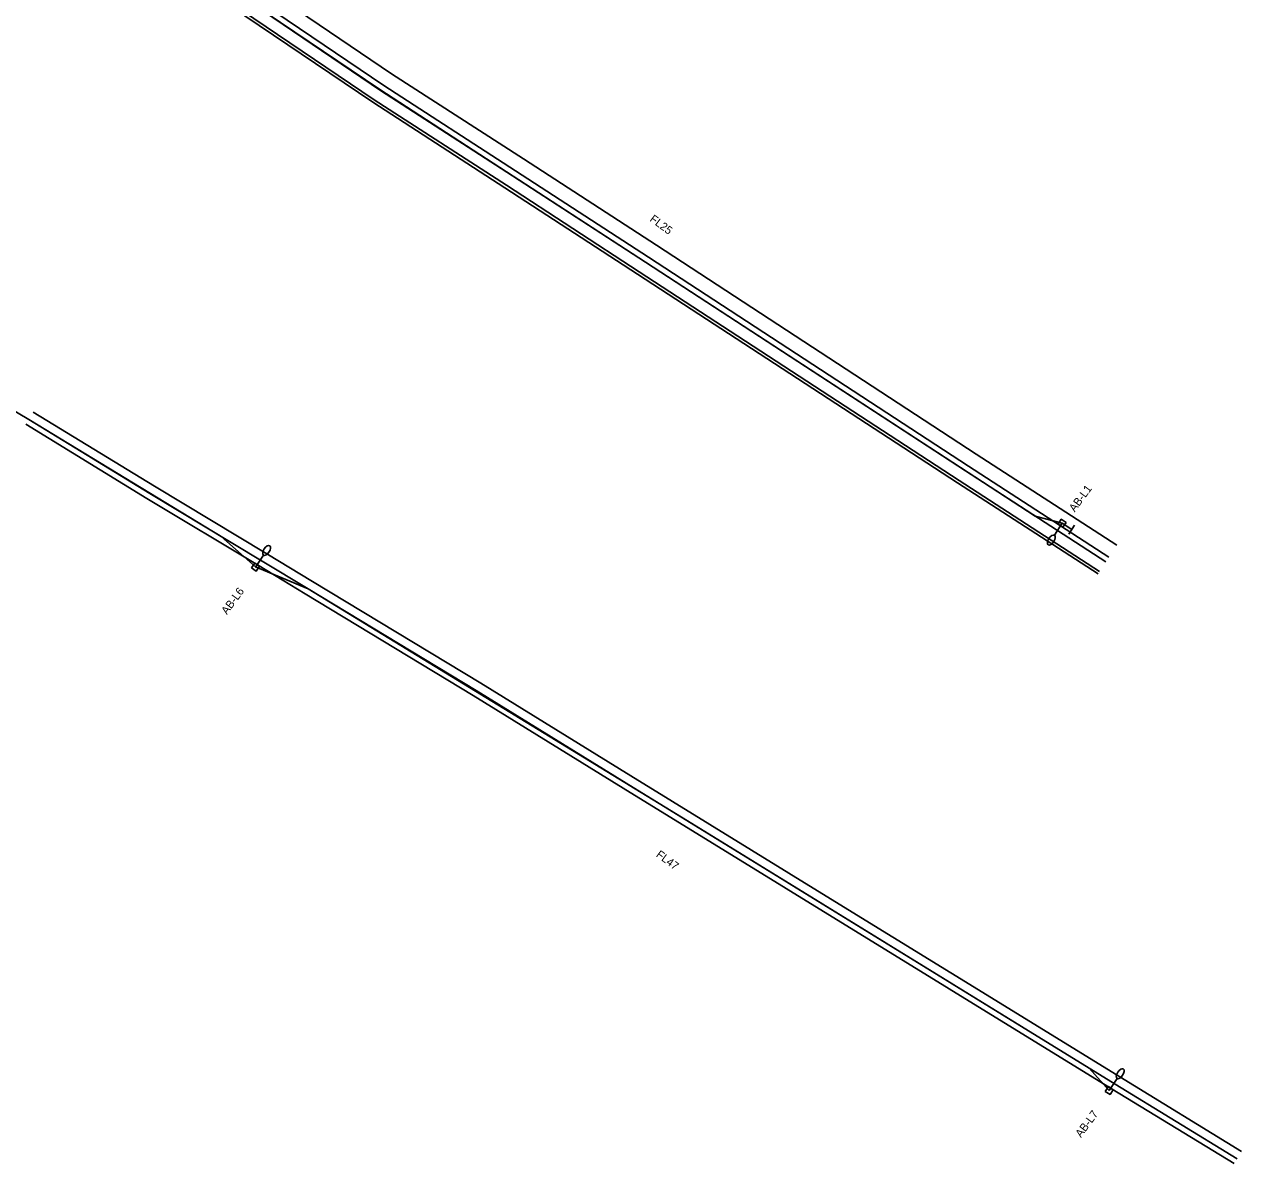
# Model space of a CAD drawing. Extents: x 1322666 to 1327584, y 458075 to 462260.
# Drawn here: x 1326186.9 to 1326612.7, y 458980.2 to 459378.6 of the extents above; entities that cross this region are included whole.
import ezdxf

# ---------------------------------------------------------------- set-up
doc = ezdxf.new("R2010")
doc.units = 0
for name, color, linetype in [('_CIVIL_CONSTRUCTION', 7, 'Continuous'), ('DR_P_Culvert3D', 7, 'Continuous'), ('PF_X_Ground_Line', 7, 'Continuous'), ('UT_X_Misc_Cells', 7, 'Continuous'), ('UT_X_Oil', 7, 'Continuous')]:
    doc.layers.add(name, color=color, linetype=linetype)

msp = doc.modelspace()

# ---------------------------------------------------------------- linework, layer by layer
at = {"layer": '_CIVIL_CONSTRUCTION'}
for p, q in [((1326549.86, 459204.14), (1326547.15, 459199.93)), ((1326267.75, 459188.82), (1326270.52, 459192.98)), ((1326566.35, 459005.74), (1326569.08, 459009.93))]:
    msp.add_line(p, q, dxfattribs=at)
for points in [[(1326551.24, 459204.44), (1326550.16, 459202.76), (1326548.48, 459203.84), (1326549.56, 459205.52)], [(1326266.36, 459188.54), (1326267.47, 459190.2), (1326269.14, 459189.1), (1326268.03, 459187.43)], [(1326564.97, 459005.45), (1326566.06, 459007.13), (1326567.73, 459006.03), (1326566.64, 459004.36)]]:
    msp.add_lwpolyline(points, close=True, dxfattribs=at)
for centre, major_axis in [((1326271.63, 459194.64), (1.11, 1.66)), ((1326546.07, 459198.25), (-1.08, -1.68)), ((1326570.18, 459011.61), (1.09, 1.67))]:
    msp.add_ellipse(centre, major_axis=major_axis, ratio=0.5, dxfattribs=at)
at = {"layer": 'DR_P_Culvert3D'}
for points in [[(1326568.96, 459196.54), (1326519.83, 459228.31), (1326407.95, 459301.35), (1326361.46, 459331.57), (1326315.37, 459361.38), (1326260.78, 459398.43), (1326183.72, 459451.96), (1326109.27, 459505.99), (1326047.67, 459552.79), (1325951.93, 459633.41), (1325920.86, 459660.88), (1325891.74, 459687.77), (1325870.28, 459708.32), (1325856.15, 459722.21), (1325848.08, 459730.28), (1325821.4, 459757.65)], [(1326562.99, 459187.31), (1326513.84, 459219.08), (1326401.95, 459292.13), (1326355.48, 459322.34), (1326309.3, 459352.21), (1326254.55, 459389.36), (1326177.35, 459442.99), (1326102.72, 459497.16), (1326040.79, 459544.19), (1325944.75, 459625.08), (1325913.49, 459652.72), (1325884.21, 459679.75), (1325862.62, 459700.43), (1325848.41, 459714.39), (1325840.25, 459722.55), (1325813.53, 459749.97)], [(1325816.39, 459752.76), (1325843.1, 459725.36), (1325851.23, 459717.24), (1325865.4, 459703.3), (1325886.95, 459682.67), (1325916.17, 459655.69), (1325947.36, 459628.11), (1326043.29, 459547.32), (1326105.1, 459500.37), (1326179.66, 459446.25), (1326256.82, 459392.66), (1326311.51, 459355.54), (1326357.66, 459325.7), (1326404.13, 459295.49), (1326516.02, 459222.44), (1326565.16, 459190.66)], [(1326566.25, 459192.34), (1326517.11, 459224.11), (1326405.22, 459297.16), (1326358.74, 459327.37), (1326312.61, 459357.21), (1326257.95, 459394.3), (1326180.82, 459447.88), (1326106.29, 459501.97), (1326044.54, 459548.88), (1325948.67, 459629.62), (1325917.51, 459657.17), (1325888.32, 459684.12), (1325866.8, 459704.73), (1325852.63, 459718.66), (1325844.52, 459726.77), (1325817.82, 459754.16)], [(1325812.81, 459749.27), (1325839.54, 459721.85), (1325847.7, 459713.68), (1325861.92, 459699.71), (1325883.52, 459679.02), (1325912.82, 459651.98), (1325944.09, 459624.32), (1326040.17, 459543.41), (1326102.12, 459496.35), (1326176.77, 459442.18), (1326253.99, 459388.53), (1326308.74, 459351.38), (1326354.94, 459321.5), (1326401.4, 459291.3), (1326513.3, 459218.24), (1326562.45, 459186.47)], [(1326188.44, 459240.49), (1326230.83, 459214.55), (1326270.12, 459190.91), (1326286.17, 459181.22), (1326344.97, 459145.65), (1326397.42, 459113.23), (1326568.45, 459007.98), (1326611.09, 458981.87)], [(1326612.66, 458984.43), (1326570.02, 459010.53), (1326532.77, 459033.46), (1326468.89, 459072.77), (1326398.99, 459115.78), (1326346.54, 459148.21), (1326287.72, 459183.79), (1326271.66, 459193.48), (1326232.39, 459217.11), (1326190, 459243.05)], [(1326187.39, 459238.79), (1326229.79, 459212.84), (1326269.08, 459189.2), (1326285.13, 459179.51), (1326343.93, 459143.94), (1326396.37, 459111.52), (1326567.4, 459006.27), (1326610.05, 458980.17)]]:
    msp.add_lwpolyline(points, dxfattribs=at)
at = {"layer": 'PF_X_Ground_Line'}
for points in [[(1326549.86, 459204.14), (1326540.44, 459206.65), (1326404.13, 459295.49), (1326311.18, 459355.82), (1326256.82, 459392.66), (1326179.66, 459446.25), (1326105.1, 459500.37), (1326059.83, 459534.69), (1326026.64, 459564.84), (1325979.09, 459610.77)], [(1326267.74, 459188.9), (1326255.73, 459199.5), (1326188.44, 459240.49), (1325968.53, 459370.86)], [(1326566.27, 459005.74), (1326559.29, 459013.62), (1326418.79, 459100.07), (1326286.17, 459181.22), (1326267.74, 459188.9)]]:
    msp.add_lwpolyline(points, dxfattribs=at)
at = {"layer": 'UT_X_Oil'}
for p, q in [((1326549.86, 459204.14), (1326553.23, 459201.96)), ((1326552.21, 459200.37), (1326554.17, 459203.42))]:
    msp.add_line(p, q, dxfattribs=at)

# ---------------------------------------------------------------- texts
at = {"layer": 'UT_X_Misc_Cells'}
for s, rotation, p in [('FL25', 323.4759, (1326405.42, 459310.03)), ('AB-L1', 53.4759, (1326554.27, 459207.89)), ('AB-L6', 53.4759, (1326257.75, 459172)), ('FL47', 323.4759, (1326407.62, 459087.75)), ('AB-L7', 53.4759, (1326556.47, 458989.12))]:
    msp.add_text(s, height=2.8, rotation=rotation, dxfattribs=at).set_placement(p)

doc.saveas('drawing.dxf')
